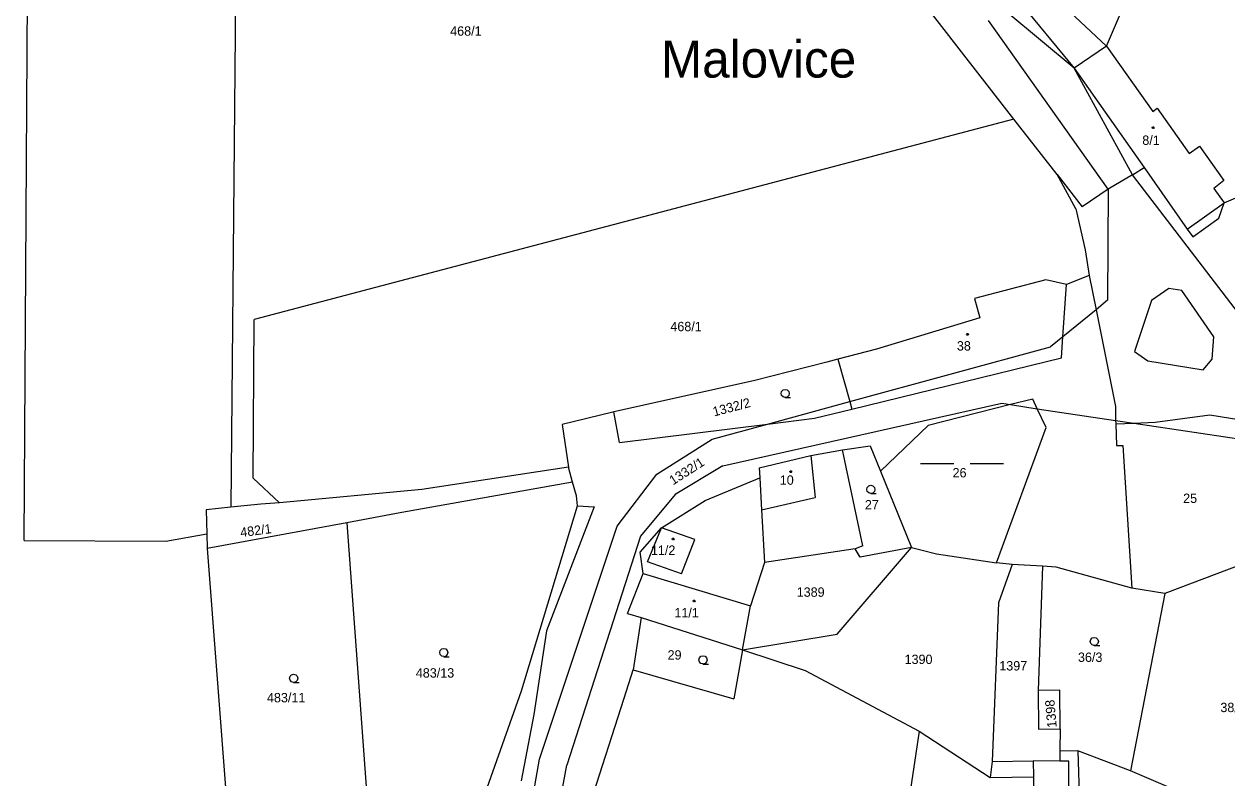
# Model space of a CAD drawing. Extents: x -845995 to -842497, y -1063614 to -1059680.
# Drawn here: x -844759.3 to -844541.5, y -1061526.1 to -1061389.6 of the extents above; entities that cross this region are included whole.
import ezdxf

# ---------------------------------------------------------------- set-up
doc = ezdxf.new("R2010")
doc.units = 0
for name, color, linetype in [('KN_HRANICE', 7, 'Continuous'), ('KN_KULTURY', 7, 'Continuous'), ('KN_PARCELY', 7, 'Continuous'), ('KN_SLUCKY', 7, 'Continuous'), ('KN_STAVEBNI', 7, 'Continuous')]:
    doc.layers.add(name, color=color, linetype=linetype)

# ---------------------------------------------------------------- blocks, each defined once
blk = doc.blocks.new('304')
blk.add_lwpolyline([(0, 0), (-0.38, 0.1), (-0.65, 0.37), (-0.75, 0.74), (-0.65, 1.11), (-0.38, 1.38), (-0.01, 1.48), (0.36, 1.38), (0.63, 1.11), (0.73, 0.73), (0.63, 0.35), (0.36, 0.08), (-0.02, -0.02), (0.98, -0.02)])
blk = doc.blocks.new('NAHRADNI_SYMBOL')
blk.add_lwpolyline([(0.09, 0.15), (0.18, 0), (0.09, -0.15), (-0.09, -0.15), (-0.18, 0), (-0.09, 0.15), (0.09, 0.15)])
blk = doc.blocks.new('803')
for p, q in [((-7.5, 0), (-1.5, 0)), ((1.5, 0), (7.5, 0))]:
    blk.add_line(p, q)
blk = doc.blocks.new('402')
blk.add_lwpolyline([(0.09, 0.15), (0.18, 0), (0.09, -0.15), (-0.09, -0.15), (-0.18, 0), (-0.09, 0.15), (0.09, 0.15)])

msp = doc.modelspace()

# ---------------------------------------------------------------- linework, layer by layer
at = {"layer": 'KN_HRANICE'}
for p, q in [((-844759.29, -1061483.09), (-844758.07, -1061297.42)), ((-844720.36, -1061310.83), (-844721.83, -1061477.08)), ((-844593.67, -1061367.85), (-844569.16, -1061397.58)), ((-844580.38, -1061377.63), (-844563.31, -1061393.54)), ((-844580.08, -1061406.78), (-844595.28, -1061387.31)), ((-844563.31, -1061393.54), (-844560.41, -1061386.81)), ((-844563.31, -1061393.54), (-844569.16, -1061397.58)), ((-844569.16, -1061397.58), (-844556.53, -1061415.56)), ((-844580.08, -1061406.78), (-844717.62, -1061443.09)), ((-844572.25, -1061416.81), (-844580.08, -1061406.78)), ((-844558.62, -1061416.89), (-844556.53, -1061415.56)), ((-844556.53, -1061415.56), (-844548.71, -1061426.69)), ((-844572.25, -1061416.81), (-844567.71, -1061422.67)), ((-844568.91, -1061423.05), (-844572.25, -1061416.81)), ((-844558.62, -1061416.89), (-844563.06, -1061419.45)), ((-844563.06, -1061419.45), (-844567.71, -1061422.67)), ((-844542.06, -1061421.97), (-844537.66, -1061420.06)), ((-844568.91, -1061423.05), (-844567.19, -1061430.48)), ((-844542.99, -1061424.72), (-844542.06, -1061421.97)), ((-844547.73, -1061428.08), (-844542.99, -1061424.72)), ((-844548.71, -1061426.69), (-844547.73, -1061428.08)), ((-844567.19, -1061430.48), (-844566.46, -1061435.08)), ((-844574.31, -1061435.87), (-844587.2, -1061439.3)), ((-844570.56, -1061436.72), (-844574.31, -1061435.87)), ((-844566.46, -1061435.08), (-844570.56, -1061436.72)), ((-844566.46, -1061435.08), (-844565.22, -1061441.3)), ((-844571.24, -1061446.2), (-844570.56, -1061436.72)), ((-844587.2, -1061439.3), (-844586.28, -1061442.8)), ((-844586.28, -1061442.8), (-844604.97, -1061448.44)), ((-844565.22, -1061441.3), (-844561.73, -1061458.84)), ((-844717.8, -1061471.84), (-844717.62, -1061443.09)), ((-844571.51, -1061450), (-844571.24, -1061446.2)), ((-844604.97, -1061448.44), (-844611.96, -1061450.29)), ((-844613.99, -1061450.83), (-844627.22, -1061454.2)), ((-844611.96, -1061450.29), (-844613.99, -1061450.83)), ((-844611.96, -1061450.29), (-844609.8, -1061457.94)), ((-844609.42, -1061459.29), (-844571.51, -1061450)), ((-844627.22, -1061454.2), (-844652.53, -1061459.81)), ((-844609.8, -1061457.94), (-844609.42, -1061459.29)), ((-844576.68, -1061457.48), (-844580.69, -1061458.5)), ((-844575.87, -1061459.23), (-844576.68, -1061457.48)), ((-844652.69, -1061459.85), (-844661.9, -1061462.12)), ((-844652.53, -1061459.81), (-844652.69, -1061459.85)), ((-844651.48, -1061465.37), (-844652.53, -1061459.81)), ((-844616.21, -1061460.95), (-844609.42, -1061459.29)), ((-844580.69, -1061458.5), (-844595.6, -1061462.3)), ((-844574.27, -1061462.65), (-844575.87, -1061459.23)), ((-844561.73, -1061458.84), (-844561.68, -1061461.36)), ((-844661.9, -1061462.12), (-844660.74, -1061469.85)), ((-844651.48, -1061465.37), (-844624.68, -1061462.01)), ((-844624.68, -1061462.01), (-844616.21, -1061460.95)), ((-844595.6, -1061462.3), (-844604.26, -1061470.57)), ((-844561.68, -1061461.36), (-844561.67, -1061462)), ((-844561.67, -1061462), (-844558.37, -1061461.86)), ((-844561.67, -1061462), (-844561.52, -1061465.91)), ((-844558.37, -1061461.86), (-844554.5, -1061461.7)), ((-844554.5, -1061461.7), (-844544.65, -1061460.34)), ((-844544.65, -1061460.34), (-844537.49, -1061461.47)), ((-844583.25, -1061487.14), (-844574.27, -1061462.65)), ((-844616.87, -1061467.72), (-844611.12, -1061466.69)), ((-844611.12, -1061466.69), (-844606.12, -1061465.95)), ((-844607.46, -1061484.06), (-844611.12, -1061466.69)), ((-844606.12, -1061465.95), (-844604.26, -1061470.57)), ((-844561.52, -1061465.91), (-844560.4, -1061465.91)), ((-844560.4, -1061465.91), (-844558.74, -1061491.73)), ((-844626.2, -1061469.92), (-844616.87, -1061467.72)), ((-844660.74, -1061469.85), (-844687.29, -1061473.84)), ((-844660.03, -1061472.53), (-844660.74, -1061469.85)), ((-844626.2, -1061469.92), (-844626.1, -1061471.78)), ((-844604.26, -1061470.57), (-844598.62, -1061484.35)), ((-844717.8, -1061471.84), (-844713.04, -1061476.31)), ((-844660.03, -1061472.53), (-844690.91, -1061478.06)), ((-844659.29, -1061474.99), (-844660.03, -1061472.53)), ((-844635.96, -1061475.84), (-844626.1, -1061471.78)), ((-844626.1, -1061471.78), (-844625.8, -1061477.58)), ((-844687.29, -1061473.84), (-844713.04, -1061476.31)), ((-844659.07, -1061476.84), (-844659.29, -1061474.99)), ((-844721.83, -1061477.08), (-844726.34, -1061477.54)), ((-844726.34, -1061477.54), (-844726.21, -1061481.89)), ((-844716.45, -1061476.54), (-844721.83, -1061477.08)), ((-844713.04, -1061476.31), (-844716.45, -1061476.54)), ((-844669.25, -1061510.34), (-844659.07, -1061476.84)), ((-844656.11, -1061476.98), (-844664.72, -1061499.45)), ((-844659.07, -1061476.84), (-844656.11, -1061476.98)), ((-844643.87, -1061480.8), (-844635.96, -1061475.84)), ((-844625.8, -1061477.58), (-844625.23, -1061487.08)), ((-844690.91, -1061478.06), (-844700.84, -1061479.9)), ((-844733.65, -1061483.23), (-844726.21, -1061481.89)), ((-844726.21, -1061481.89), (-844726.14, -1061484.58)), ((-844700.84, -1061479.9), (-844726.14, -1061484.58)), ((-844700.84, -1061479.9), (-844695.93, -1061547.63)), ((-844647.74, -1061485.2), (-844643.87, -1061480.8)), ((-844646.4, -1061486.96), (-844643.87, -1061480.8)), ((-844637.85, -1061482.93), (-844643.87, -1061480.8)), ((-844759.29, -1061483.09), (-844733.65, -1061483.23)), ((-844640.3, -1061489.16), (-844637.85, -1061482.93)), ((-844607.46, -1061484.06), (-844608.86, -1061484.63)), ((-844726.14, -1061484.58), (-844721.31, -1061547.47)), ((-844647.22, -1061489.07), (-844647.74, -1061485.2)), ((-844608.86, -1061484.63), (-844625.23, -1061487.08)), ((-844612.11, -1061500.09), (-844598.62, -1061484.35)), ((-844607.93, -1061486.13), (-844608.86, -1061484.63)), ((-844598.62, -1061484.35), (-844607.93, -1061486.13)), ((-844598.62, -1061484.35), (-844596.96, -1061484.81)), ((-844596.96, -1061484.81), (-844594.13, -1061485.5)), ((-844594.13, -1061485.5), (-844583.25, -1061487.14)), ((-844533.17, -1061485.27), (-844552.79, -1061492.69)), ((-844640.3, -1061489.16), (-844646.4, -1061486.96)), ((-844625.23, -1061487.08), (-844627.77, -1061494.95)), ((-844580.39, -1061487.47), (-844583.25, -1061487.14)), ((-844580.39, -1061487.47), (-844582.89, -1061494.41)), ((-844574.94, -1061487.74), (-844580.39, -1061487.47)), ((-844574.94, -1061487.74), (-844575.71, -1061510.27)), ((-844572.44, -1061487.93), (-844574.94, -1061487.74)), ((-844558.74, -1061491.73), (-844572.44, -1061487.93)), ((-844650.03, -1061496.31), (-844647.22, -1061489.07)), ((-844552.79, -1061492.69), (-844559.01, -1061524.82)), ((-844552.79, -1061492.69), (-844558.74, -1061491.73)), ((-844629.2, -1061502.88), (-844627.77, -1061494.95)), ((-844582.89, -1061494.41), (-844584.01, -1061523.15)), ((-844650.03, -1061496.31), (-844647.56, -1061497.06)), ((-844647.56, -1061497.06), (-844649.02, -1061506.53)), ((-844647.56, -1061497.06), (-844629.2, -1061502.88)), ((-844664.72, -1061499.45), (-844667, -1061514.65)), ((-844629.2, -1061502.88), (-844612.11, -1061500.09)), ((-844629.2, -1061502.88), (-844630.81, -1061511.79)), ((-844629.2, -1061502.88), (-844617.88, -1061506.63)), ((-844650.67, -1061511.68), (-844649.02, -1061506.53)), ((-844649.02, -1061506.53), (-844630.81, -1061511.79)), ((-844617.88, -1061506.63), (-844597.26, -1061517.65)), ((-844571.81, -1061510.23), (-844575.71, -1061510.27)), ((-844575.71, -1061510.27), (-844575.64, -1061517.27)), ((-844571.74, -1061517.23), (-844571.81, -1061510.23)), ((-844676.11, -1061529.78), (-844669.25, -1061510.34)), ((-844656.75, -1061530.65), (-844650.67, -1061511.68)), ((-844667, -1061514.65), (-844669.29, -1061526.62)), ((-844597.26, -1061517.65), (-844605.93, -1061575.54)), ((-844597.26, -1061517.65), (-844584.4, -1061526.05)), ((-844575.64, -1061517.27), (-844571.74, -1061517.23)), ((-844571.74, -1061517.23), (-844571.77, -1061521.17)), ((-844571.77, -1061521.17), (-844571.79, -1061523.05)), ((-844571.77, -1061521.17), (-844568.5, -1061521.23)), ((-844584.01, -1061523.15), (-844576.61, -1061523.02)), ((-844576.61, -1061523.02), (-844576.55, -1061525.94)), ((-844571.79, -1061523.05), (-844576.61, -1061523.02)), ((-844568.5, -1061521.23), (-844568.15, -1061533.97)), ((-844559.01, -1061524.82), (-844568.5, -1061521.23)), ((-844529.43, -1061537.42), (-844559.01, -1061524.82)), ((-844584.4, -1061526.05), (-844576.55, -1061525.94)), ((-844576.55, -1061525.94), (-844576.36, -1061539.23))]:
    msp.add_line(p, q, dxfattribs=at)
at = {"layer": 'KN_SLUCKY'}
for p, q in [((-844569.16, -1061397.58), (-844581.36, -1061387.39)), ((-844563.06, -1061419.45), (-844584.67, -1061388.89)), ((-844563.31, -1061393.54), (-844554.96, -1061405.39)), ((-844558.62, -1061416.89), (-844569.16, -1061397.58)), ((-844554.96, -1061405.39), (-844554.15, -1061404.81)), ((-844554.15, -1061404.81), (-844548.39, -1061412.98)), ((-844548.39, -1061412.98), (-844546.51, -1061411.66)), ((-844546.51, -1061411.66), (-844542.07, -1061417.88)), ((-844532.72, -1061450.71), (-844558.62, -1061416.89)), ((-844542.07, -1061417.88), (-844543.9, -1061419.36)), ((-844563.06, -1061419.45), (-844563.13, -1061439.59)), ((-844543.9, -1061419.36), (-844542.06, -1061421.97)), ((-844548.71, -1061426.69), (-844542.06, -1061421.97)), ((-844552.06, -1061437.44), (-844555.2, -1061439.65)), ((-844549.68, -1061437.82), (-844552.06, -1061437.44)), ((-844543.9, -1061446.22), (-844549.68, -1061437.82)), ((-844563.13, -1061439.59), (-844565.22, -1061441.3)), ((-844555.2, -1061439.65), (-844558.26, -1061448.9)), ((-844565.22, -1061441.3), (-844571.24, -1061446.2)), ((-844571.24, -1061446.2), (-844573.45, -1061448)), ((-844544.19, -1061450.24), (-844543.9, -1061446.22)), ((-844609.8, -1061457.94), (-844573.45, -1061448)), ((-844558.26, -1061448.9), (-844555.86, -1061450.54)), ((-844555.86, -1061450.54), (-844545.86, -1061452.19)), ((-844545.86, -1061452.19), (-844544.19, -1061450.24)), ((-844624.68, -1061462.01), (-844609.8, -1061457.94)), ((-844632.78, -1061469.59), (-844582.31, -1061458.26)), ((-844582.31, -1061458.26), (-844580.69, -1061458.5)), ((-844580.69, -1061458.5), (-844575.87, -1061459.23)), ((-844575.87, -1061459.23), (-844561.68, -1061461.36)), ((-844634.73, -1061464.76), (-844624.68, -1061462.01)), ((-844561.68, -1061461.36), (-844558.37, -1061461.86)), ((-844558.37, -1061461.86), (-844538.17, -1061464.9)), ((-844644.73, -1061471.07), (-844634.73, -1061464.76)), ((-844616.87, -1061467.72), (-844616.07, -1061475.32)), ((-844651.89, -1061480.51), (-844644.73, -1061471.07)), ((-844632.78, -1061469.59), (-844641.42, -1061474.8)), ((-844641.42, -1061474.8), (-844647.72, -1061482.35)), ((-844625.8, -1061477.58), (-844616.07, -1061475.32)), ((-844665.98, -1061522.69), (-844651.89, -1061480.51)), ((-844647.72, -1061482.35), (-844661.05, -1061523.77)), ((-844647.22, -1061489.07), (-844627.77, -1061494.95)), ((-844671.44, -1061554.37), (-844665.98, -1061522.69)), ((-844584.01, -1061523.15), (-844584.4, -1061526.05)), ((-844570.17, -1061523.06), (-844571.79, -1061523.05)), ((-844570.1, -1061539.27), (-844570.17, -1061523.06)), ((-844666.26, -1061551.77), (-844661.05, -1061523.77))]:
    msp.add_line(p, q, dxfattribs=at)
at = {"layer": 'KN_STAVEBNI'}
for p, q in [((-844563.31, -1061393.54), (-844569.16, -1061397.58)), ((-844563.31, -1061393.54), (-844554.96, -1061405.39)), ((-844569.16, -1061397.58), (-844556.53, -1061415.56)), ((-844554.96, -1061405.39), (-844554.15, -1061404.81)), ((-844554.15, -1061404.81), (-844548.39, -1061412.98)), ((-844548.39, -1061412.98), (-844546.51, -1061411.66)), ((-844546.51, -1061411.66), (-844542.07, -1061417.88)), ((-844556.53, -1061415.56), (-844548.71, -1061426.69)), ((-844542.07, -1061417.88), (-844543.9, -1061419.36)), ((-844543.9, -1061419.36), (-844542.06, -1061421.97)), ((-844548.71, -1061426.69), (-844542.06, -1061421.97)), ((-844626.2, -1061469.92), (-844616.87, -1061467.72)), ((-844616.87, -1061467.72), (-844616.07, -1061475.32)), ((-844626.2, -1061469.92), (-844626.1, -1061471.78)), ((-844626.1, -1061471.78), (-844625.8, -1061477.58)), ((-844625.8, -1061477.58), (-844616.07, -1061475.32)), ((-844646.4, -1061486.96), (-844643.87, -1061480.8)), ((-844637.85, -1061482.93), (-844643.87, -1061480.8)), ((-844640.3, -1061489.16), (-844637.85, -1061482.93)), ((-844640.3, -1061489.16), (-844646.4, -1061486.96)), ((-844650.03, -1061496.31), (-844647.22, -1061489.07)), ((-844647.22, -1061489.07), (-844627.77, -1061494.95)), ((-844629.2, -1061502.88), (-844627.77, -1061494.95)), ((-844650.03, -1061496.31), (-844647.56, -1061497.06)), ((-844647.56, -1061497.06), (-844629.2, -1061502.88)), ((-844571.79, -1061523.05), (-844576.61, -1061523.02)), ((-844576.61, -1061523.02), (-844576.55, -1061525.94)), ((-844570.17, -1061523.06), (-844571.79, -1061523.05)), ((-844570.1, -1061539.27), (-844570.17, -1061523.06)), ((-844576.55, -1061525.94), (-844576.36, -1061539.23))]:
    msp.add_line(p, q, dxfattribs=at)

# ---------------------------------------------------------------- block references
at = {"layer": 'KN_KULTURY'}
for name, p in [('402', (-844554.91, -1061408.33)), ('NAHRADNI_SYMBOL', (-844588.49, -1061445.75)), ('304', (-844621.49, -1061457.21)), ('402', (-844620.5, -1061470.65)), ('803', (-844589.49, -1061469.18)), ('304', (-844605.99, -1061474.59)), ('402', (-844641.79, -1061482.81)), ('402', (-844638, -1061494.04)), ('304', (-844565.54, -1061502.13)), ('304', (-844683.3, -1061504.13)), ('304', (-844636.37, -1061505.46)), ('304', (-844710.48, -1061508.8))]:
    msp.add_blockref(name, p, dxfattribs=at)

# ---------------------------------------------------------------- texts
at = {"layer": 'KN_PARCELY'}
for s, height, p in [('468/1', 1.7, (-844682.15, -1061391.67)), ('Malovice', 6.7, (-844643.99, -1061399.26)), ('8/1', 1.7, (-844556.85, -1061411.45)), ('468/1', 1.7, (-844642.29, -1061445.2)), ('38', 1.7, (-844590.42, -1061448.7)), ('26', 1.7, (-844591.2, -1061471.68)), ('10', 1.7, (-844622.48, -1061473.01)), ('25', 1.7, (-844549.46, -1061476.31)), ('27', 1.7, (-844607.08, -1061477.48)), ('11/2', 1.7, (-844645.81, -1061485.71)), ('1389', 1.7, (-844619.42, -1061493.3)), ('11/1', 1.7, (-844641.56, -1061497.04)), ('29', 1.7, (-844642.79, -1061504.68)), ('1390', 1.7, (-844599.89, -1061505.48)), ('36/3', 1.7, (-844568.5, -1061505.1)), ('1397', 1.7, (-844582.75, -1061506.65)), ('483/13', 1.7, (-844688.37, -1061507.94)), ('483/11', 1.7, (-844715.32, -1061512.42)), ('38/1', 1.7, (-844542.72, -1061514.19))]:
    msp.add_text(s, height=height, dxfattribs=at).set_placement(p)
for s, rotation, p in [('1332/2', 14.725, (-844634.37, -1061460.65)), ('1332/1', 32.659, (-844641.8, -1061473.13)), ('482/1', 7.334, (-844720.04, -1061482.49)), ('1398', 94.996, (-844572.34, -1061516.92))]:
    msp.add_text(s, height=1.7, rotation=rotation, dxfattribs=at).set_placement(p)

doc.saveas('drawing.dxf')
